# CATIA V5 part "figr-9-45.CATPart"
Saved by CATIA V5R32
Part number: Part1
Bounding box of the stored display mesh (mm): x -159.661 to 182.627, y -78.048 to 78.048, z 0 to 72.429
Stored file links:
  D:\PROJECTS\Project 2022\CATIA V5 6R 2022\Resources\Part Files\c09_catia_v5_6r2022_prt\c09_catia_v5_6r2022_prt\figr-9-45.CATPart
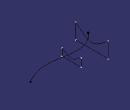
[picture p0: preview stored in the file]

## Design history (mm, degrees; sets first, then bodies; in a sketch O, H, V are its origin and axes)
Body1 (main body)
  Plane1: type Offset, RefPlane yz-plane, Offset 100
  Plane2: type Offset, RefPlane yz-plane, Offset 100, reversed
  Sketch1 on Plane1, origin (100, 0, 0), H (0, 1, 0), V (0, 0, 1)
    point P1 (0, 15.965)
    hyperbola C1
    point P2 (0, 3.0416)
    line L1 (54.8261, 44.8858) -> (54.8261, 0)
    point P5 (54.8261, 0)
    line L2 (-54.8261, 44.8858) -> (-54.8261, 0)
    point P6 (-54.8261, 0)
    line L3 (-54.8261, 0) -> (54.8261, 0)
    coincidence: P1 V, P2 V, P5 H, P6 H
    vertical: L1 V, L2 V
    horizontal: L3 H
  Sketch2 on xy-plane, origin (0, 0, 0), H (1, 0, 0), V (0, 1, 0)
    spline S1 through (-159.6608, -77.1468) (-77.8466, -31.8169) (23.6283, -41.4968) (182.6271, -11.7333)
  Sketch3 on yz-plane, origin (0, 0, 0), H (0, 1, 0), V (0, 0, 1)
    point P1 (0, 18.9787)
    hyperbola C1
    point P2 (0, 2.6681)
    line L1 (48.2237, 37.1764) -> (48.2237, 0)
    point P5 (48.2237, 0)
    line L2 (-43.6563, 34.1546) -> (-43.6563, 0)
    point P6 (-43.6563, 0)
    line L3 (-43.6563, 0) -> (48.2237, 0)
    coincidence: P1 V, P2 V, P5 H, P6 H
    vertical: L1 V, L2 V
    horizontal: L3 H
  Sketch4 on Plane2, origin (-100, 0, 0), H (0, 1, 0), V (0, 0, 1)
    point P1 (0, 140.6052)
    point P2 (0, 41.8972)
    hyperbola C1
    line L1 (78.0478, 72.4293) -> (78.0478, 0)
    point P5 (78.0478, 0)
    line L2 (-78.0478, 72.4293) -> (-78.0478, 0)
    point P6 (-78.0478, 0)
    line L3 (-78.0478, 0) -> (78.0478, 0)
    coincidence: P1 V, P2 V, P5 H, P6 H
    vertical: L1 V, L2 V
    horizontal: L3 H
  Loft1: solid, Sections (Sketch3; Sketch4), Spine Sketch2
